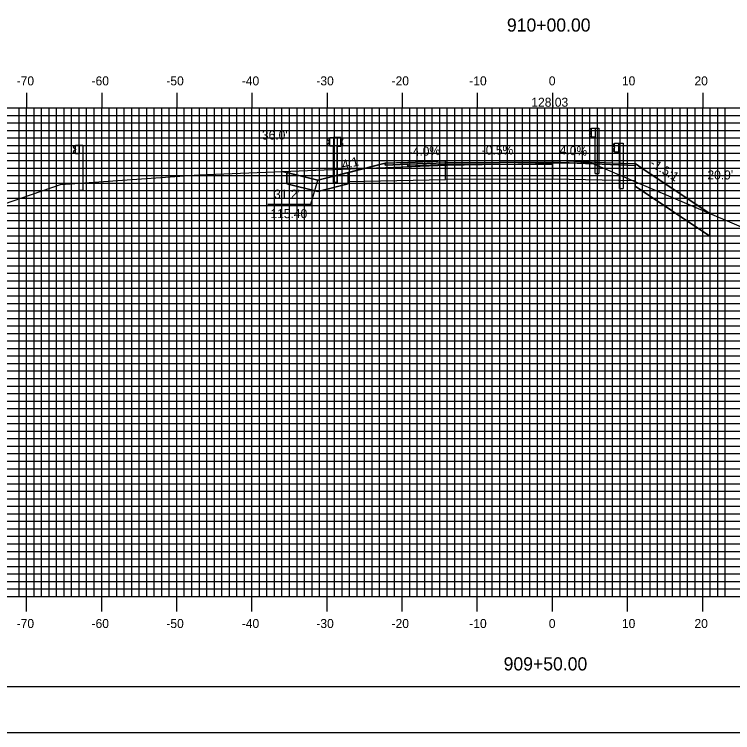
# Model space of a CAD drawing. Extents: x 859078 to 859421, y 364765 to 364985.
# Drawn here: x 859171.7 to 859267.3, y 364765.2 to 364860.7 of the extents above; entities that cross this region are included whole.
import ezdxf

# ---------------------------------------------------------------- set-up
doc = ezdxf.new("R2010")
doc.units = 0
for name, color, linetype in [('ANNOTATION', 7, 'Continuous'), ('BORDER', 7, 'Continuous'), ('D_Guardrail_Beam_Rt', 7, 'Continuous'), ('D_Roadway_Centerline', 7, 'Continuous'), ('D_Roadway_Centerline_Text', 7, 'Continuous'), ('D_Roadway_Edge_Shoulder', 7, 'Continuous'), ('D_Roadway_Edge_TW', 7, 'Continuous'), ('D_Roadway_FinishedGrade', 7, 'Continuous'), ('D_Roadway_Pavement', 7, 'Continuous'), ('D_Roadway_SubGrade', 7, 'Continuous'), ('D_Text_Standard', 7, 'Continuous'), ('H_V ANNOTATION', 7, 'Continuous'), ('M_Guardrail', 7, 'Continuous'), ('M_Roadway_Centerline', 7, 'Continuous'), ('MAJOR', 7, 'Continuous'), ('MINOR', 7, 'Continuous'), ('PATTERNING', 7, 'Continuous'), ('PLOT BOUNDARY', 7, 'Continuous'), ('S_Roadway_Centerline', 7, 'Continuous')]:
    doc.layers.add(name, color=color, linetype=linetype)

msp = doc.modelspace()

# ---------------------------------------------------------------- linework, layer by layer
at = {"layer": 'ANNOTATION'}
msp.add_lwpolyline([(859205.49, 364835.51), (859211.181, 364835.51), (859212.153, 364838.699)], dxfattribs=at)
at = {"layer": 'BORDER'}
msp.add_lwpolyline([(859093.76, 364771.302), (859413.76, 364771.302), (859413.76, 364981.302), (859093.76, 364981.302)], close=True, dxfattribs=at)
at = {"layer": 'D_Guardrail_Beam_Rt'}
for p, q in [((859251.541, 364843.488), (859251.398, 364843.388)), ((859251.631, 364843.509), (859251.557, 364843.495)), ((859251.631, 364843.593), (859252.319, 364843.593)), ((859251.631, 364842.426), (859251.631, 364843.593)), ((859252.152, 364843.593), (859252.152, 364842.426)), ((859252.256, 364843.593), (859252.256, 364842.426)), ((859252.319, 364843.593), (859252.79, 364843.593)), ((859252.319, 364843.593), (859252.319, 364842.426)), ((859252.79, 364843.593), (859252.79, 364837.593)), ((859251.398, 364843.245), (859251.593, 364843.109)), ((859251.593, 364842.91), (859251.398, 364842.774)), ((859251.398, 364842.63), (859251.541, 364842.53)), ((859251.557, 364842.524), (859251.631, 364842.509)), ((859251.627, 364843.044), (859251.627, 364842.974)), ((859252.319, 364842.426), (859251.631, 364842.426)), ((859252.298, 364837.593), (859252.298, 364842.426)), ((859252.298, 364837.593), (859252.79, 364837.593))]:
    msp.add_line(p, q, dxfattribs=at)
for centre, major_axis, start_param, end_param in [((859251.448, 364843.316), (-0.0877, 0), 5.323254, 7.243116), ((859251.565, 364843.454), (-0.0417, 0), 4.907132, 5.323254), ((859251.448, 364842.702), (-0.0877, 0), 5.323254, 7.243116), ((859251.565, 364842.564), (-0.0417, 0), 0.959931, 1.376053), ((859251.548, 364843.044), (0.0789, 0), 0, 0.959931), ((859251.548, 364842.974), (0.0789, 0), 5.323254, 6.283185)]:
    msp.add_ellipse(centre, major_axis=major_axis, ratio=0.995501, start_param=start_param, end_param=end_param, dxfattribs=at)
at = {"layer": 'D_Roadway_Centerline'}
msp.add_line((859221.112, 364840.939), (859212.153, 364838.699), dxfattribs=at)
for points in [[(859212.153, 364838.699), (859216.632, 364839.819), (859221.112, 364840.939), (859223.401, 364841.031), (859224.113, 364841.059), (859224.117, 364841.059), (859229.112, 364841.259), (859229.24, 364841.26), (859243.36, 364841.329), (859249.023, 364841.103), (859251.36, 364841.009), (859252.462, 364840.965), (859254.342, 364840.89), (859254.36, 364840.889), (859264.33, 364834.242)], [(859207.4, 364839.844), (859212.153, 364838.699)]]:
    msp.add_lwpolyline(points, dxfattribs=at)
at = {"layer": 'D_Roadway_Edge_Shoulder'}
for points in [[(859229.112, 364841.259), (859224.113, 364841.059), (859224.113, 364841.059), (859221.112, 364840.939), (859221.112, 364840.689), (859224.113, 364840.809), (859229.112, 364841.009)], [(859243.36, 364841.329), (859251.36, 364841.009), (859251.36, 364841.009), (859254.36, 364840.889), (859254.36, 364840.639), (859243.36, 364841.079)]]:
    msp.add_lwpolyline(points, close=True, dxfattribs=at)
at = {"layer": 'D_Roadway_Edge_TW'}
msp.add_lwpolyline([(859229.112, 364841.259), (859243.36, 364841.329), (859243.36, 364841.079), (859229.112, 364841.009)], close=True, dxfattribs=at)
at = {"layer": 'D_Roadway_FinishedGrade'}
msp.add_line((859254.36, 364840.889), (859254.36, 364837.889), dxfattribs=at)
for points in [[(859254.36, 364840.889), (859255.86, 364839.889), (859264.33, 364834.242)], [(859264.33, 364834.242), (859264.33, 364831.242), (859254.36, 364837.889)]]:
    msp.add_lwpolyline(points, dxfattribs=at)
for points in [[(859216.153, 364839.699), (859216.153, 364838.199), (859212.153, 364837.199), (859208.001, 364838.199), (859208.001, 364839.699), (859212.153, 364838.699)], [(859216.153, 364839.699), (859212.153, 364838.699), (859208.001, 364839.699), (859208.001, 364838.199), (859212.153, 364837.199), (859216.153, 364838.199)]]:
    msp.add_lwpolyline(points, close=True, dxfattribs=at)
at = {"layer": 'D_Roadway_Pavement'}
for points in [[(859229.112, 364841.009), (859224.113, 364840.809), (859224.113, 364840.559), (859229.112, 364840.759)], [(859229.112, 364841.009), (859243.36, 364841.079), (859243.36, 364840.829), (859229.112, 364840.759)]]:
    msp.add_lwpolyline(points, close=True, dxfattribs=at)
msp.add_lwpolyline([(859243.36, 364841.079), (859243.36, 364840.829)], dxfattribs=at)
msp.add_lwpolyline([(859243.36, 364841.079), (859243.36, 364840.829)], dxfattribs=at)
msp.add_lwpolyline([(859243.36, 364841.079), (859243.36, 364840.829)], dxfattribs=at)
at = {"layer": 'D_Roadway_SubGrade'}
for points in [[(859229.112, 364840.759), (859224.113, 364840.559), (859224.113, 364840.809), (859221.112, 364840.689), (859221.112, 364840.939), (859216.153, 364839.699), (859216.153, 364838.501), (859229.112, 364838.759)], [(859229.112, 364840.759), (859243.36, 364840.829), (859243.36, 364838.829), (859229.112, 364838.759)], [(859243.36, 364840.829), (859243.36, 364841.079), (859254.36, 364840.639), (859254.36, 364840.889), (859254.36, 364838.609), (859243.36, 364838.829)]]:
    msp.add_lwpolyline(points, close=True, dxfattribs=at)
at = {"layer": 'M_Guardrail'}
for p, q in [((859248.447, 364845.505), (859248.303, 364845.405)), ((859248.303, 364845.262), (859248.499, 364845.125)), ((859248.546, 364845.526), (859248.464, 364845.511)), ((859248.546, 364845.599), (859249.035, 364845.599)), ((859248.546, 364844.432), (859248.546, 364845.599)), ((859249.035, 364845.599), (859249.527, 364845.599)), ((859249.035, 364845.599), (859249.035, 364844.432)), ((859249.527, 364845.599), (859249.527, 364839.599)), ((859213.613, 364844.274), (859213.469, 364844.174)), ((859213.712, 364844.295), (859213.63, 364844.281)), ((859213.712, 364844.368), (859214.201, 364844.368)), ((859213.712, 364843.201), (859213.712, 364844.368)), ((859214.201, 364844.368), (859214.693, 364844.368)), ((859214.201, 364844.368), (859214.201, 364843.201)), ((859214.215, 364844.382), (859214.215, 364838.382)), ((859214.707, 364844.382), (859214.215, 364844.382)), ((859214.693, 364844.368), (859214.693, 364838.368)), ((859215.196, 364844.382), (859214.707, 364844.382)), ((859214.707, 364844.382), (859214.707, 364843.216)), ((859215.196, 364843.216), (859215.196, 364844.382)), ((859215.196, 364844.31), (859215.278, 364844.295)), ((859215.295, 364844.288), (859215.438, 364844.188)), ((859248.499, 364844.906), (859248.303, 364844.769)), ((859248.303, 364844.626), (859248.447, 364844.526)), ((859248.464, 364844.519), (859248.546, 364844.505)), ((859248.533, 364845.061), (859248.533, 364844.97)), ((859249.035, 364844.432), (859248.546, 364844.432)), ((859249.035, 364839.599), (859249.035, 364844.432)), ((859179.866, 364843.362), (859180.356, 364843.362)), ((859179.866, 364842.195), (859179.866, 364843.362)), ((859180.356, 364843.362), (859180.847, 364843.362)), ((859180.356, 364843.362), (859180.356, 364842.195)), ((859180.847, 364843.362), (859180.847, 364837.362)), ((859213.469, 364844.031), (859213.665, 364843.895)), ((859213.665, 364843.675), (859213.469, 364843.539)), ((859213.469, 364843.395), (859213.613, 364843.295)), ((859213.698, 364843.83), (859213.698, 364843.739)), ((859215.209, 364843.845), (859215.209, 364843.754)), ((859215.438, 364844.045), (859215.243, 364843.909)), ((859215.243, 364843.689), (859215.438, 364843.553)), ((859215.438, 364843.41), (859215.295, 364843.31)), ((859179.767, 364843.268), (859179.624, 364843.168)), ((859179.624, 364843.025), (859179.819, 364842.889)), ((859179.819, 364842.669), (859179.624, 364842.533)), ((859179.624, 364842.39), (859179.767, 364842.29)), ((859179.866, 364843.289), (859179.784, 364843.275)), ((859179.853, 364842.824), (859179.853, 364842.733)), ((859213.63, 364843.289), (859213.712, 364843.274)), ((859214.201, 364843.201), (859213.712, 364843.201)), ((859214.201, 364838.368), (859214.201, 364843.201)), ((859214.707, 364838.382), (859214.707, 364843.216)), ((859214.707, 364843.216), (859215.196, 364843.216)), ((859215.278, 364843.303), (859215.196, 364843.289)), ((859179.784, 364842.283), (859179.866, 364842.268)), ((859180.356, 364842.195), (859179.866, 364842.195)), ((859180.356, 364837.362), (859180.356, 364842.195)), ((859249.035, 364839.599), (859249.527, 364839.599)), ((859214.201, 364838.368), (859214.693, 364838.368)), ((859214.707, 364838.382), (859214.215, 364838.382)), ((859180.356, 364837.362), (859180.847, 364837.362))]:
    msp.add_line(p, q, dxfattribs=at)
for centre, major_axis, start_param, end_param in [((859248.354, 364845.333), (-0.0877, 0), 5.323254, 7.243116), ((859248.471, 364845.471), (-0.0417, 0), 4.886922, 5.323254), ((859213.637, 364844.24), (-0.0417, 0), 4.886922, 5.323254), ((859215.271, 364844.254), (0.0417, 0), 0.959931, 1.396263), ((859248.354, 364844.698), (-0.0877, 0), 5.323254, 7.243116), ((859248.471, 364844.56), (-0.0417, 0), 0.959931, 1.396263), ((859248.454, 364845.061), (0.0789, 0), 0, 0.959931), ((859248.454, 364844.97), (0.0789, 0), 5.323254, 6.283185), ((859213.52, 364844.102), (-0.0877, 0), 5.323254, 7.243116), ((859213.52, 364843.467), (-0.0877, 0), 5.323254, 7.243116), ((859213.619, 364843.83), (0.0789, 0), 0, 0.959931), ((859213.619, 364843.739), (0.0789, 0), 5.323254, 6.283185), ((859215.288, 364843.845), (-0.0789, 0), 5.323254, 6.283185), ((859215.288, 364843.754), (-0.0789, 0), 6.283185, 7.243116), ((859215.388, 364844.117), (0.0877, 0), 5.323254, 7.243116), ((859215.388, 364843.481), (0.0877, 0), 5.323254, 7.243116), ((859179.674, 364843.096), (-0.0877, 0), 5.323254, 7.243116), ((859179.674, 364842.461), (-0.0877, 0), 5.323254, 7.243116), ((859179.791, 364843.234), (-0.0417, 0), 4.886922, 5.323254), ((859179.774, 364842.824), (0.0789, 0), 0, 0.959931), ((859179.774, 364842.733), (0.0789, 0), 5.323254, 6.283185), ((859213.637, 364843.329), (-0.0417, 0), 0.959931, 1.396263), ((859215.271, 364843.344), (0.0417, 0), 4.886922, 5.323254), ((859179.791, 364842.324), (-0.0417, 0), 0.959931, 1.396263)]:
    msp.add_ellipse(centre, major_axis=major_axis, ratio=0.995501, start_param=start_param, end_param=end_param, dxfattribs=at)
at = {"layer": 'MAJOR'}
for p, q in [((859173.36, 364850.306), (859173.36, 364848.302)), ((859183.36, 364850.306), (859183.36, 364848.302)), ((859193.36, 364850.306), (859193.36, 364848.302)), ((859203.36, 364850.306), (859203.36, 364848.302)), ((859213.36, 364850.306), (859213.36, 364848.302)), ((859223.36, 364850.306), (859223.36, 364848.302)), ((859233.36, 364850.306), (859233.36, 364848.302)), ((859243.36, 364850.306), (859243.36, 364848.302)), ((859253.36, 364850.306), (859253.36, 364848.302)), ((859263.36, 364850.306), (859263.36, 364848.302)), ((859103.36, 364848.302), (859383.36, 364848.302)), ((859103.36, 364848.302), (859383.36, 364848.302)), ((859173.36, 364783.302), (859173.36, 364848.302)), ((859183.36, 364783.302), (859183.36, 364848.302)), ((859193.36, 364783.302), (859193.36, 364848.302)), ((859203.36, 364783.302), (859203.36, 364848.302)), ((859213.36, 364783.302), (859213.36, 364848.302)), ((859223.36, 364783.302), (859223.36, 364848.302)), ((859233.36, 364783.302), (859233.36, 364848.302)), ((859243.36, 364783.302), (859243.36, 364848.302)), ((859253.36, 364783.302), (859253.36, 364848.302)), ((859263.36, 364783.302), (859263.36, 364848.302)), ((859103.36, 364843.302), (859383.36, 364843.302)), ((859103.36, 364838.302), (859383.36, 364838.302)), ((859103.36, 364833.302), (859383.36, 364833.302)), ((859103.36, 364828.302), (859383.36, 364828.302)), ((859103.36, 364823.302), (859383.36, 364823.302)), ((859103.36, 364818.302), (859383.36, 364818.302)), ((859103.36, 364813.302), (859383.36, 364813.302)), ((859103.36, 364808.302), (859383.36, 364808.302)), ((859103.36, 364803.302), (859383.36, 364803.302)), ((859103.36, 364798.302), (859383.36, 364798.302)), ((859103.36, 364793.302), (859383.36, 364793.302)), ((859103.36, 364788.302), (859383.36, 364788.302)), ((859103.36, 364783.302), (859383.36, 364783.302)), ((859103.36, 364783.302), (859383.36, 364783.302)), ((859173.36, 364781.298), (859173.36, 364783.302)), ((859183.36, 364781.298), (859183.36, 364783.302)), ((859193.36, 364781.298), (859193.36, 364783.302)), ((859203.36, 364781.298), (859203.36, 364783.302)), ((859213.36, 364781.298), (859213.36, 364783.302)), ((859223.36, 364781.298), (859223.36, 364783.302)), ((859233.36, 364781.298), (859233.36, 364783.302)), ((859243.36, 364781.298), (859243.36, 364783.302)), ((859253.36, 364781.298), (859253.36, 364783.302)), ((859263.36, 364781.298), (859263.36, 364783.302))]:
    msp.add_line(p, q, dxfattribs=at)
at = {"layer": 'MINOR'}
for p, q in [((859172.36, 364783.302), (859172.36, 364848.302)), ((859174.36, 364783.302), (859174.36, 364848.302)), ((859175.36, 364783.302), (859175.36, 364848.302)), ((859176.36, 364783.302), (859176.36, 364848.302)), ((859177.36, 364783.302), (859177.36, 364848.302)), ((859178.36, 364783.302), (859178.36, 364848.302)), ((859179.36, 364783.302), (859179.36, 364848.302)), ((859180.36, 364783.302), (859180.36, 364848.302)), ((859181.36, 364783.302), (859181.36, 364848.302)), ((859182.36, 364783.302), (859182.36, 364848.302)), ((859184.36, 364783.302), (859184.36, 364848.302)), ((859185.36, 364783.302), (859185.36, 364848.302)), ((859186.36, 364783.302), (859186.36, 364848.302)), ((859187.36, 364783.302), (859187.36, 364848.302)), ((859188.36, 364783.302), (859188.36, 364848.302)), ((859189.36, 364783.302), (859189.36, 364848.302)), ((859190.36, 364783.302), (859190.36, 364848.302)), ((859191.36, 364783.302), (859191.36, 364848.302)), ((859192.36, 364783.302), (859192.36, 364848.302)), ((859194.36, 364783.302), (859194.36, 364848.302)), ((859195.36, 364783.302), (859195.36, 364848.302)), ((859196.36, 364783.302), (859196.36, 364848.302)), ((859197.36, 364783.302), (859197.36, 364848.302)), ((859198.36, 364783.302), (859198.36, 364848.302)), ((859199.36, 364783.302), (859199.36, 364848.302)), ((859200.36, 364783.302), (859200.36, 364848.302)), ((859201.36, 364783.302), (859201.36, 364848.302)), ((859202.36, 364783.302), (859202.36, 364848.302)), ((859204.36, 364783.302), (859204.36, 364848.302)), ((859205.36, 364783.302), (859205.36, 364848.302)), ((859206.36, 364783.302), (859206.36, 364848.302)), ((859207.36, 364783.302), (859207.36, 364848.302)), ((859208.36, 364783.302), (859208.36, 364848.302)), ((859209.36, 364783.302), (859209.36, 364848.302)), ((859210.36, 364783.302), (859210.36, 364848.302)), ((859211.36, 364783.302), (859211.36, 364848.302)), ((859212.36, 364783.302), (859212.36, 364848.302)), ((859214.36, 364783.302), (859214.36, 364848.302)), ((859215.36, 364783.302), (859215.36, 364848.302)), ((859216.36, 364783.302), (859216.36, 364848.302)), ((859217.36, 364783.302), (859217.36, 364848.302)), ((859218.36, 364783.302), (859218.36, 364848.302)), ((859219.36, 364783.302), (859219.36, 364848.302)), ((859220.36, 364783.302), (859220.36, 364848.302)), ((859221.36, 364783.302), (859221.36, 364848.302)), ((859222.36, 364783.302), (859222.36, 364848.302)), ((859224.36, 364783.302), (859224.36, 364848.302)), ((859225.36, 364783.302), (859225.36, 364848.302)), ((859226.36, 364783.302), (859226.36, 364848.302)), ((859227.36, 364783.302), (859227.36, 364848.302)), ((859228.36, 364783.302), (859228.36, 364848.302)), ((859229.36, 364783.302), (859229.36, 364848.302)), ((859230.36, 364783.302), (859230.36, 364848.302)), ((859231.36, 364783.302), (859231.36, 364848.302)), ((859232.36, 364783.302), (859232.36, 364848.302)), ((859234.36, 364783.302), (859234.36, 364848.302)), ((859235.36, 364783.302), (859235.36, 364848.302)), ((859236.36, 364783.302), (859236.36, 364848.302)), ((859237.36, 364783.302), (859237.36, 364848.302)), ((859238.36, 364783.302), (859238.36, 364848.302)), ((859239.36, 364783.302), (859239.36, 364848.302)), ((859240.36, 364783.302), (859240.36, 364848.302)), ((859241.36, 364783.302), (859241.36, 364848.302)), ((859242.36, 364783.302), (859242.36, 364848.302)), ((859244.36, 364783.302), (859244.36, 364848.302)), ((859245.36, 364783.302), (859245.36, 364848.302)), ((859246.36, 364783.302), (859246.36, 364848.302)), ((859247.36, 364783.302), (859247.36, 364848.302)), ((859248.36, 364783.302), (859248.36, 364848.302)), ((859249.36, 364783.302), (859249.36, 364848.302)), ((859250.36, 364783.302), (859250.36, 364848.302)), ((859251.36, 364783.302), (859251.36, 364848.302)), ((859252.36, 364783.302), (859252.36, 364848.302)), ((859254.36, 364783.302), (859254.36, 364848.302)), ((859255.36, 364783.302), (859255.36, 364848.302)), ((859256.36, 364783.302), (859256.36, 364848.302)), ((859257.36, 364783.302), (859257.36, 364848.302)), ((859258.36, 364783.302), (859258.36, 364848.302)), ((859259.36, 364783.302), (859259.36, 364848.302)), ((859260.36, 364783.302), (859260.36, 364848.302)), ((859261.36, 364783.302), (859261.36, 364848.302)), ((859262.36, 364783.302), (859262.36, 364848.302)), ((859264.36, 364783.302), (859264.36, 364848.302)), ((859265.36, 364783.302), (859265.36, 364848.302)), ((859266.36, 364783.302), (859266.36, 364848.302)), ((859103.36, 364847.302), (859383.36, 364847.302)), ((859103.36, 364846.302), (859383.36, 364846.302)), ((859103.36, 364845.302), (859383.36, 364845.302)), ((859103.36, 364844.302), (859383.36, 364844.302)), ((859103.36, 364842.302), (859383.36, 364842.302)), ((859103.36, 364841.302), (859383.36, 364841.302)), ((859103.36, 364840.302), (859383.36, 364840.302)), ((859103.36, 364839.302), (859383.36, 364839.302)), ((859103.36, 364837.302), (859383.36, 364837.302)), ((859103.36, 364836.302), (859383.36, 364836.302)), ((859103.36, 364835.302), (859383.36, 364835.302)), ((859103.36, 364834.302), (859383.36, 364834.302)), ((859103.36, 364832.302), (859383.36, 364832.302)), ((859103.36, 364831.302), (859383.36, 364831.302)), ((859103.36, 364830.302), (859383.36, 364830.302)), ((859103.36, 364829.302), (859383.36, 364829.302)), ((859103.36, 364827.302), (859383.36, 364827.302)), ((859103.36, 364826.302), (859383.36, 364826.302)), ((859103.36, 364825.302), (859383.36, 364825.302)), ((859103.36, 364824.302), (859383.36, 364824.302)), ((859103.36, 364822.302), (859383.36, 364822.302)), ((859103.36, 364821.302), (859383.36, 364821.302)), ((859103.36, 364820.302), (859383.36, 364820.302)), ((859103.36, 364819.302), (859383.36, 364819.302)), ((859103.36, 364817.302), (859383.36, 364817.302)), ((859103.36, 364816.302), (859383.36, 364816.302)), ((859103.36, 364815.302), (859383.36, 364815.302)), ((859103.36, 364814.302), (859383.36, 364814.302)), ((859103.36, 364812.302), (859383.36, 364812.302)), ((859103.36, 364811.302), (859383.36, 364811.302)), ((859103.36, 364810.302), (859383.36, 364810.302)), ((859103.36, 364809.302), (859383.36, 364809.302)), ((859103.36, 364807.302), (859383.36, 364807.302)), ((859103.36, 364806.302), (859383.36, 364806.302)), ((859103.36, 364805.302), (859383.36, 364805.302)), ((859103.36, 364804.302), (859383.36, 364804.302)), ((859103.36, 364802.302), (859383.36, 364802.302)), ((859103.36, 364801.302), (859383.36, 364801.302)), ((859103.36, 364800.302), (859383.36, 364800.302)), ((859103.36, 364799.302), (859383.36, 364799.302)), ((859103.36, 364797.302), (859383.36, 364797.302)), ((859103.36, 364796.302), (859383.36, 364796.302)), ((859103.36, 364795.302), (859383.36, 364795.302)), ((859103.36, 364794.302), (859383.36, 364794.302)), ((859103.36, 364792.302), (859383.36, 364792.302)), ((859103.36, 364791.302), (859383.36, 364791.302)), ((859103.36, 364790.302), (859383.36, 364790.302)), ((859103.36, 364789.302), (859383.36, 364789.302)), ((859103.36, 364787.302), (859383.36, 364787.302)), ((859103.36, 364786.302), (859383.36, 364786.302)), ((859103.36, 364785.302), (859383.36, 364785.302)), ((859103.36, 364784.302), (859383.36, 364784.302))]:
    msp.add_line(p, q, dxfattribs=at)
at = {"layer": 'PATTERNING'}
for p, q in [((859255.86, 364839.889), (859254.36, 364840.889)), ((859264.33, 364834.242), (859255.86, 364839.889)), ((859254.36, 364838.609), (859254.36, 364837.889))]:
    msp.add_line(p, q, dxfattribs=at)
for points in [[(859254.36, 364840.889), (859254.36, 364840.639), (859254.36, 364838.609), (859254.36, 364838.609)], [(859254.36, 364837.889), (859264.33, 364831.242), (859264.33, 364834.242)]]:
    msp.add_lwpolyline(points, dxfattribs=at)
at = {"layer": 'PLOT BOUNDARY'}
msp.add_lwpolyline([(859077.573, 364765.184), (859417.573, 364765.184), (859417.573, 364985.184), (859077.573, 364985.184)], close=True, dxfattribs=at)
at = {"layer": 'S_Roadway_Centerline'}
msp.add_lwpolyline([(859103.36, 364813.597), (859104.311, 364813.538), (859113.143, 364813.681), (859124.184, 364814.817), (859131.019, 364817.14), (859139.866, 364820.639), (859142.899, 364821.986), (859144.014, 364822.533), (859160.904, 364831.396), (859165.442, 364833.812), (859166.501, 364834.214), (859177.889, 364838.109), (859179.794, 364838.242), (859196.275, 364839.41), (859212.997, 364840.052), (859229.266, 364840.688), (859248.223, 364841.049), (859248.392, 364841.052), (859248.584, 364840.972), (859269.616, 364831.984)], dxfattribs=at)

# ---------------------------------------------------------------- texts
at = {"layer": 'ANNOTATION'}
for s, rotation, p in [('-4.0%', 2.29095, (859224.246, 364841.866)), ('-0.5%', 0.28145, (859233.957, 364842.083)), ('4.0%', 357.70957, (859244.304, 364842.093)), ('4:1', 14.03624, (859215.502, 364840.127)), ('-1.5:1', 327.88116, (859256.242, 364840.646))]:
    msp.add_text(s, height=1.2, rotation=rotation, dxfattribs=at).set_placement(p)
for s, p in [("31.2' ", (859206.305, 364836.236)), ('115.40', (859205.818, 364833.636))]:
    msp.add_text(s, height=1.2, dxfattribs=at).set_placement(p)
at = {"layer": 'D_Roadway_Centerline_Text'}
msp.add_text('128.03', height=1.2, dxfattribs=at).set_placement((859240.551, 364848.46))
at = {"layer": 'D_Text_Standard'}
for s, p in [("36.0'", (859204.685, 364844.092)), ("20.9'", (859263.988, 364838.786))]:
    msp.add_text(s, height=1.2, dxfattribs=at).set_placement(p)
at = {"layer": 'H_V ANNOTATION'}
for s, height, p in [('910+00.00', 1.75, (859237.305, 364858.458)), ('-70', 1.2, (859172.043, 364851.302)), ('-60', 1.2, (859182.011, 364851.302)), ('-50', 1.2, (859191.968, 364851.302)), ('-40', 1.2, (859202.011, 364851.302)), ('-30', 1.2, (859211.936, 364851.302)), ('-20', 1.2, (859221.947, 364851.302)), ('-10', 1.2, (859232.29, 364851.302)), ('0', 1.2, (859242.878, 364851.302)), ('10', 1.2, (859252.611, 364851.302)), ('20', 1.2, (859262.268, 364851.302)), ('-70', 1.2, (859172.043, 364779.102)), ('-60', 1.2, (859182.011, 364779.102)), ('-50', 1.2, (859191.968, 364779.102)), ('-40', 1.2, (859202.011, 364779.102)), ('-30', 1.2, (859211.936, 364779.102)), ('-20', 1.2, (859221.947, 364779.102)), ('-10', 1.2, (859232.29, 364779.102)), ('0', 1.2, (859242.878, 364779.102)), ('10', 1.2, (859252.611, 364779.102)), ('20', 1.2, (859262.268, 364779.102)), ('909+50.00', 1.75, (859236.868, 364773.458))]:
    msp.add_text(s, height=height, dxfattribs=at).set_placement(p)
at = {"layer": 'M_Roadway_Centerline'}
for s, p in [('C', (859229.261, 364840.688)), ('L', (859229.266, 364840.681)), ('C', (859196.27, 364839.41)), ('L', (859196.275, 364839.402))]:
    msp.add_text(s, height=0.0146, dxfattribs=at).set_placement(p)

doc.saveas('drawing.dxf')
